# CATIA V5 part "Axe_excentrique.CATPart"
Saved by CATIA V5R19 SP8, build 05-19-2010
Part number: Axe_excentrique
Revision: ANY
Definition: UNKNOWN
Nomenclature: 18
Source: Unknown
Bounding box of the stored display mesh (mm): x -2 to 2, y -2 to 2, z 0 to 19
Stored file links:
  D:\Documents\1_Travail\2- 2I2D\1 - Cours et TD\2- TD\3-TD Assemblage\Pompe AirMan\Axe_excentrique.CATPart
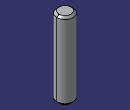
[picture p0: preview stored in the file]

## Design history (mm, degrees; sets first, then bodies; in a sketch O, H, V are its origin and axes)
Body1 "Chanfrein1" (main body)
  Solid1: solid without history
